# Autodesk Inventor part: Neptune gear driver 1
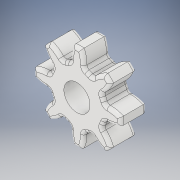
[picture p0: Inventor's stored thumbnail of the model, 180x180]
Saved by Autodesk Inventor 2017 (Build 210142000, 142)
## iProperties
Created: 2016-05
Part Number: Neptune gear driver 1
Material: Generic
Document SubType Name: Modeling
Designer: Stan
Density: 1 g/cm^3
Appearance: White
Author: Stan
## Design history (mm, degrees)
sketch "Sketch1"
  geometry: A1 r 6.91 centre (0, 0) between (-2.187, 6.554) and (-3.088, 6.181); A2 r 6.91 centre (0, 0) between (-6.181, 3.088) and (-6.554, 2.187); A3 r 6.91 centre (0, 0) between (-6.554, -2.187) and (-6.181, -3.088); A4 r 6.91 centre (0, 0) between (-3.088, -6.181) and (-2.187, -6.554); A5 r 6.91 centre (0, 0) between (2.187, -6.554) and (3.088, -6.181); A6 r 6.91 centre (0, 0) between (6.181, -3.088) and (6.554, -2.187); A7 r 6.91 centre (0, 0) between (6.554, 2.187) and (6.181, 3.088); A8 r 6.91 centre (0, 0) between (3.088, 6.181) and (2.187, 6.554); A9 r 12.44 centre (0, -1.866) between (0.976, 10.536) and (-0.976, 10.536); A10 r 7.658 centre (-6.013, 7.405) between (1.645, 7.316) and (0.976, 10.536); A11 r 7.658 centre (6.013, 7.405) between (-0.976, 10.536) and (-1.645, 7.305); A12 r 0.794 centre (2.438, 7.307) between (1.645, 7.316) and (2.187, 6.554); A13 r 0.794 centre (-2.438, 7.307) between (-2.187, 6.554) and (-1.645, 7.316); A14 r 12.44 centre (1.32, -1.32) between (-6.76, 8.14) and (-8.14, 6.76); A15 r 7.658 centre (-9.488, 0.984) between (-4.01, 6.336) and (-6.76, 8.14); A16 r 7.658 centre (-0.984, 9.488) between (-8.14, 6.76) and (-6.329, 4.003); A17 r 0.794 centre (-3.443, 6.891) between (-4.01, 6.336) and (-3.088, 6.181); A18 r 0.794 centre (-6.891, 3.443) between (-6.181, 3.088) and (-6.336, 4.01); A19 r 12.44 centre (1.866, 0) between (-10.536, 0.976) and (-10.536, -0.976); A20 r 7.658 centre (-7.405, -6.013) between (-7.316, 1.645) and (-10.536, 0.976); A21 r 7.658 centre (-7.405, 6.013) between (-10.536, -0.976) and (-7.305, -1.645); A22 r 0.794 centre (-7.307, 2.438) between (-7.316, 1.645) and (-6.554, 2.187); A23 r 0.794 centre (-7.307, -2.438) between (-6.554, -2.187) and (-7.316, -1.645); A24 r 12.44 centre (1.32, 1.32) between (-8.14, -6.76) and (-6.76, -8.14); A25 r 7.658 centre (-0.984, -9.488) between (-6.336, -4.01) and (-8.14, -6.76); A26 r 7.658 centre (-9.488, -0.984) between (-6.76, -8.14) and (-4.003, -6.329); A27 r 0.794 centre (-6.891, -3.443) between (-6.336, -4.01) and (-6.181, -3.088); A28 r 0.794 centre (-3.443, -6.891) between (-3.088, -6.181) and (-4.01, -6.336); A29 r 12.44 centre (0, 1.866) between (-0.976, -10.536) and (0.976, -10.536); A30 r 7.658 centre (6.013, -7.405) between (-1.645, -7.316) and (-0.976, -10.536); A31 r 7.658 centre (-6.013, -7.405) between (0.976, -10.536) and (1.645, -7.305); A32 r 0.794 centre (-2.438, -7.307) between (-1.645, -7.316) and (-2.187, -6.554); A33 r 0.794 centre (2.438, -7.307) between (2.187, -6.554) and (1.645, -7.316); A34 r 12.44 centre (-1.32, 1.32) between (6.76, -8.14) and (8.14, -6.76); A35 r 7.658 centre (9.488, -0.984) between (4.01, -6.336) and (6.76, -8.14); A36 r 7.658 centre (0.984, -9.488) between (8.14, -6.76) and (6.329, -4.003); A37 r 0.794 centre (3.443, -6.891) between (4.01, -6.336) and (3.088, -6.181); A38 r 0.794 centre (6.891, -3.443) between (6.181, -3.088) and (6.336, -4.01); A39 r 12.44 centre (-1.866, 0) between (10.536, -0.976) and (10.536, 0.976); A40 r 7.658 centre (7.405, 6.013) between (7.316, -1.645) and (10.536, -0.976); A41 r 7.658 centre (7.405, -6.013) between (10.536, 0.976) and (7.305, 1.645); A42 r 0.794 centre (7.307, -2.438) between (7.316, -1.645) and (6.554, -2.187); A43 r 0.794 centre (7.307, 2.438) between (6.554, 2.187) and (7.316, 1.645); A44 r 12.44 centre (-1.32, -1.32) between (8.14, 6.76) and (6.76, 8.14); A45 r 7.658 centre (0.984, 9.488) between (6.336, 4.01) and (8.14, 6.76); A46 r 7.658 centre (9.488, 0.984) between (6.76, 8.14) and (4.003, 6.329); A47 r 0.794 centre (6.891, 3.443) between (6.336, 4.01) and (6.181, 3.088); A48 r 0.794 centre (3.443, 6.891) between (3.088, 6.181) and (4.01, 6.336); 1 further point
  constraints: 104 point on circle, 48 centre point
extrude "Extrusion1" new body sketch "Sketch1" distance "d0" = 6.35; taper "d1" = 0 deg
sketch "Sketch2"
  geometry: C1 r 3.175 at (0, 0); 1 further point
  constraints: 1 centre point, 1 coincident
  dimensions: "d2" = 6.35 diameter of C1
extrude "Extrusion2" cut sketch "Sketch2" distance "d3" = 6.35; taper "d4" = 0 deg
fillet "Fillet1" dims "d5" = 0.79375
body "Solid1"
